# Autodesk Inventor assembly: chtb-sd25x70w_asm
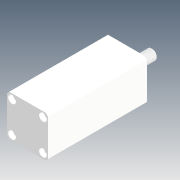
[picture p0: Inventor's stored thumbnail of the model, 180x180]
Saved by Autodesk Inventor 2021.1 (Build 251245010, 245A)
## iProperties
Company: Microsoft
Created: 2018-05
Part Number: chtb-sd25x70w_asm
Description: STEP AP214
Document SubType Name: Assembly
Designer: user
Title: chtb-sd25x70w_asm.STEP
Author: Windows
Revision Number: ÈÎºÎ
Sending System: SolidWorks 2015
Preprocessor: SwSTEP 2.0
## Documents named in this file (4)
- D:\Vault_2016\Projekty\Clamptek\Hydraulic\CHTB\CHTB-25\Inventor\chtb-sd25x70w\chtb-sd25x70w_asm.iam
- D:\Vault_2016\Projekty\Clamptek\Hydraulic\CHTB\CHTB-25\Inventor\chtb-sd25x70w\CHTB-25QG.ipt
- D:\Vault_2016\Projekty\Clamptek\Hydraulic\CHTB\CHTB-25\Inventor\chtb-sd25x70w\CHTB-SD25X70NBT.ipt
- D:\Vault_2016\Projekty\Clamptek\Hydraulic\CHTB\CHTB-25\Inventor\chtb-sd25x70w\CHTB-SD25X70WHSG.ipt
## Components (3 placed, 3 different names)
1. CHTB-25QG_1
2. CHTB-SD25X70NBT_2
3. CHTB-SD25X70WHSG_3
